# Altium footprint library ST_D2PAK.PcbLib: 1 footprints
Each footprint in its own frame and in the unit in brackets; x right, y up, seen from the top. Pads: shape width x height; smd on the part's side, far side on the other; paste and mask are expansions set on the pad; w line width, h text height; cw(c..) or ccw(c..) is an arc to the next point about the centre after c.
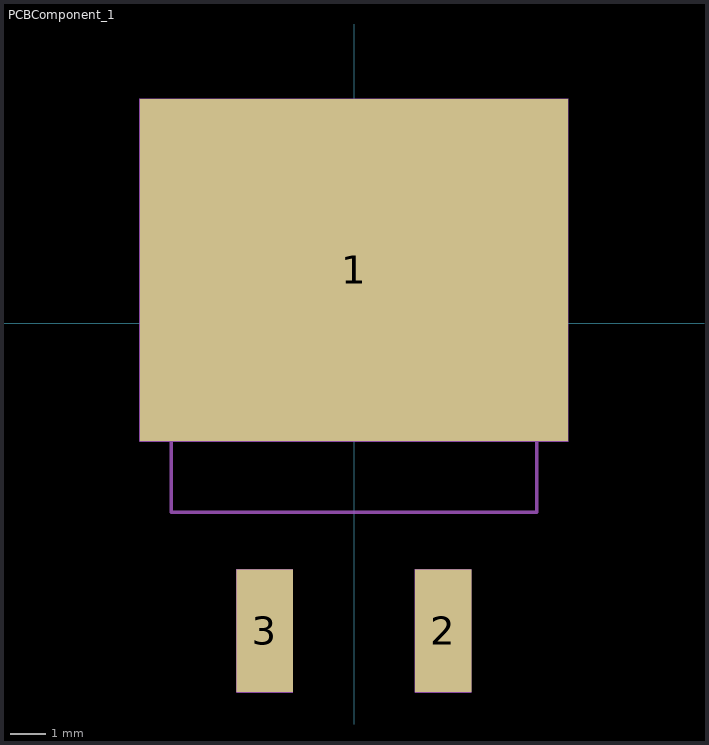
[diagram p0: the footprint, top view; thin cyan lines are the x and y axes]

## PCBComponent_1 [mm]
pads (3):
  rect 12.2x9.75 smd: 1(0,1.524)
  rect 1.6x3.5 smd: 2(2.54,-8.751) 3(-2.54,-8.751)
Mechanical 2:
  lines w0.001: -6.1,-3.351 -6.1,6.399 6.1,6.399 6.1,-3.351 -6.1,-3.351 ; -3.34,-10.501 -3.34,-7.001 -1.74,-7.001 -1.74,-10.501 -3.34,-10.501 ; 1.74,-10.501 1.74,-7.001 3.34,-7.001 3.34,-10.501 1.74,-10.501
Mechanical 4 (Mech15):
  lines w0.1: -5.2,-5.375 -5.2,5.375 5.2,5.375 5.2,-5.375 -5.2,-5.375
3D body "ST_D2PAK.step": height 4.45, standoff -0.09, extent -5.09,-9.991 5.09,5.429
